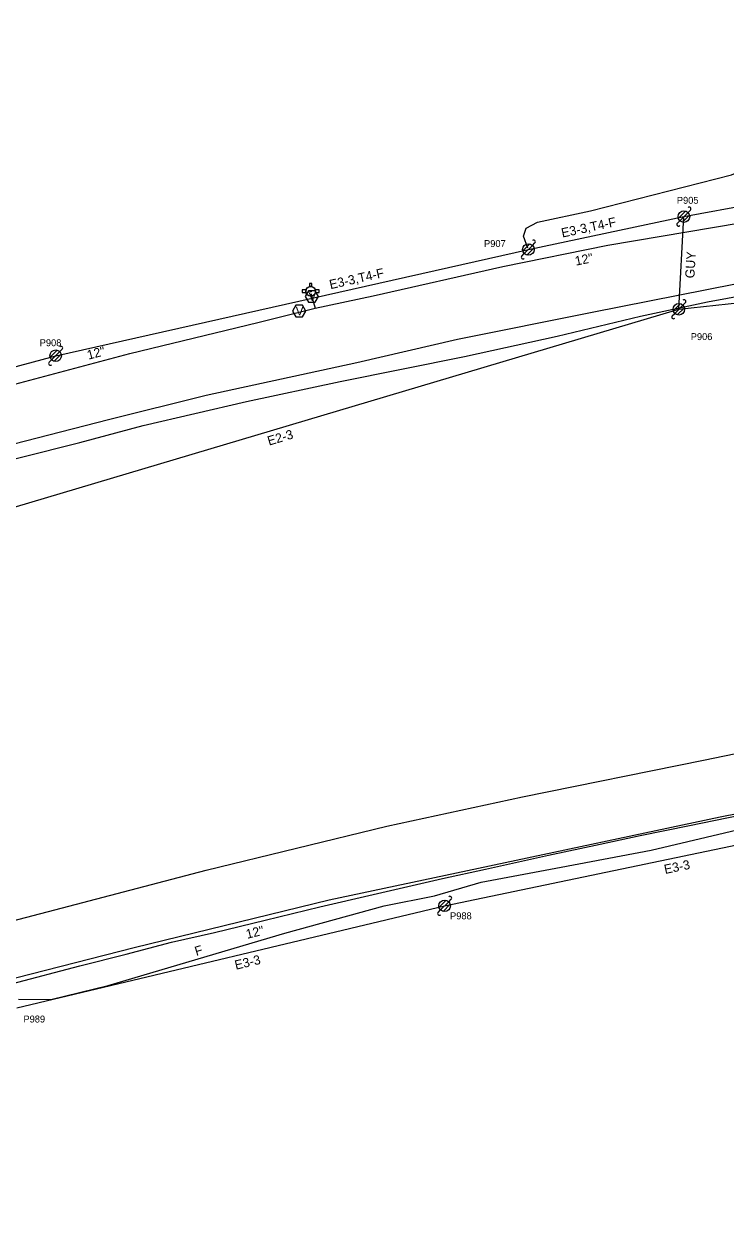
# Model space of a CAD drawing. Extents: x 1741604 to 1825760, y 1164229 to 1194908.
# Drawn here: x 1797026 to 1797330, y 1187911 to 1188433 of the extents above; entities that cross this region are included whole.
import ezdxf

# ---------------------------------------------------------------- set-up
doc = ezdxf.new("R2010")
doc.units = 0
for name, color, linetype in [('RD_EX_SU_Elec', 7, 'Continuous'), ('RD_EX_SU_Gas', 7, 'Continuous'), ('RD_EX_SU_H2O', 7, 'Continuous'), ('RD_EX_SU_Ovhd', 7, 'Continuous'), ('RD_EX_SU_Pole', 7, 'Continuous'), ('RD_EX_SU_Telecom', 7, 'Continuous'), ('RD_EX_SU_TX_H2O', 7, 'Continuous'), ('RD_EX_SU_TX_Pole', 7, 'Continuous'), ('RD_EX_SU_TX_Telecom', 7, 'Continuous')]:
    doc.layers.add(name, color=color, linetype=linetype)

# ---------------------------------------------------------------- blocks, each defined once
blk = doc.blocks.new('SUE_WFH')
at = {"layer": 'RD_EX_SU_H2O'}
for p, q in [((-2.01, 0.6), (-3.65, 0.6)), ((-3.65, 0.6), (-3.65, -0.45)), ((-0.48, 3.38), (-0.48, 2.04)), ((0.57, 3.38), (-0.48, 3.38)), ((0.57, 2.02), (0.57, 3.38)), ((3.7, 0.6), (2.01, 0.6)), ((3.7, -0.45), (3.7, 0.6)), ((-3.65, -0.45), (-2.05, -0.45)), ((2.05, -0.45), (3.7, -0.45))]:
    blk.add_line(p, q, dxfattribs=at)
for radius in [2.1, 0.263]:
    blk.add_circle((0, 0), radius, dxfattribs=at)
for start, end in [(163.3387, 192.315), (74.2455, 103.2128), (347.685, 16.6613)]:
    blk.add_arc((0, 0), 2.1, start, end, dxfattribs=at)
blk = doc.blocks.new('SUE_WV')
at = {"layer": 'RD_EX_SU_H2O'}
blk.add_lwpolyline([(2.89, 0), (1.44, 2.5), (-1.44, 2.5), (-2.89, 0), (-1.44, -2.5), (1.44, -2.5)], close=True, dxfattribs=at)
blk.add_text('V', height=3.75, dxfattribs=at).set_placement((-1.43, -1.88))
blk = doc.blocks.new('SUE_PP')
at = {"layer": 'RD_EX_SU_Pole'}
for p, q in [((-2.41, -0.65), (0.65, 2.41)), ((-1.77, -1.77), (1.77, 1.77)), ((-0.65, -2.41), (2.41, 0.65)), ((1.77, 1.77), (2.83, 2.83)), ((-2.83, -2.83), (-1.77, -1.77))]:
    blk.add_line(p, q, dxfattribs=at)
blk.add_circle((0, 0), 2.5, dxfattribs=at)
for centre, start, end in [((2.3, 3.36), 315, 135), ((-2.3, -3.36), 135, 315)]:
    blk.add_arc(centre, 0.75, start, end, dxfattribs=at)

msp = doc.modelspace()

# ---------------------------------------------------------------- linework, layer by layer
at = {"layer": 'RD_EX_SU_Elec'}
msp.add_lwpolyline([(1797244.36, 1188335.69), (1797242.43, 1188340.91), (1797243.62, 1188344.36), (1797248.47, 1188347.06), (1797271.46, 1188351.92), (1797332.51, 1188367.48), (1797339.83, 1188370.66), (1797346.01, 1188378.93), (1797354.24, 1188382.3), (1797365.1, 1188383.61), (1797373.13, 1188384.12)], dxfattribs=at)
at = {"layer": 'RD_EX_SU_Gas'}
for points in [[(1796999.22, 1188238.71), (1797050.44, 1188251.64), (1797077.75, 1188259.02), (1797122.56, 1188269.33), (1797163.15, 1188277.98), (1797216.98, 1188288.79), (1797257.11, 1188297.58), (1797293.17, 1188306.24), (1797322.16, 1188312.53), (1797378.04, 1188322.78), (1797422.78, 1188329.89), (1797468.29, 1188337.79), (1797507.29, 1188344.04), (1797536.09, 1188348.16), (1797575.83, 1188353.54), (1797616.9, 1188360.18), (1797661.37, 1188365.53), (1797707.78, 1188370.84), (1797750.95, 1188375.94), (1797792.89, 1188381.02), (1797883.32, 1188390.89)], [(1796656.1, 1187911.21), (1796700.26, 1187926.24), (1796776.05, 1187949.97), (1796853.24, 1187973.45), (1796908.86, 1187989.52), (1796990.78, 1188011.87), (1797073.97, 1188032.99), (1797158.33, 1188053.63), (1797222.98, 1188067.43), (1797327.66, 1188089.58), (1797395.86, 1188103.05), (1797465.31, 1188115.89), (1797490.6, 1188120.59), (1797504.29, 1188121.55), (1797523.16, 1188120.37), (1797539.47, 1188121.55), (1797556.07, 1188120.37), (1797575.66, 1188121.89)]]:
    msp.add_lwpolyline(points, dxfattribs=at)
at = {"layer": 'RD_EX_SU_H2O'}
for points in [[(1797150.37, 1188316.12), (1797152.28, 1188309.78), (1797177.44, 1188315.15), (1797233.5, 1188327.84), (1797278.93, 1188337.07), (1797336.23, 1188346.78), (1797380.95, 1188356.35), (1797444.61, 1188369.17), (1797512.17, 1188378.38), (1797550.95, 1188385.16), (1797589.68, 1188391.31), (1797635.24, 1188397.02), (1797695.71, 1188404.5), (1797752.4, 1188412.16), (1797828.2, 1188420.96), (1797864.18, 1188424.5), (1797870.03, 1188425), (1797870.01, 1188429.58), (1797869.79, 1188432.74)], [(1796441.83, 1188109.93), (1796444.87, 1188101.29), (1796539.94, 1188133.72), (1796647.13, 1188169.94), (1796712.18, 1188190.57), (1796798.06, 1188216.42), (1796872.26, 1188237.32), (1796925.71, 1188251.76), (1796989.63, 1188268.23), (1797072.11, 1188290.16), (1797127.52, 1188303.54), (1797152.28, 1188309.78)], [(1797020.74, 1188017.27), (1797050.38, 1188025.03), (1797070.49, 1188030.17), (1797090.04, 1188035.3), (1797108.74, 1188039.51), (1797130.56, 1188044.84), (1797154.31, 1188050.59), (1797177.42, 1188056.02), (1797207.46, 1188062.85), (1797225.98, 1188066.97), (1797253.33, 1188072.94), (1797275.68, 1188077.76), (1797293.01, 1188081.5), (1797314.36, 1188085.8), (1797336.2, 1188090.35), (1797355.18, 1188094.27), (1797378.17, 1188098.87), (1797401.5, 1188103.47), (1797420.73, 1188107.13), (1797437.47, 1188110.13), (1797458.81, 1188113.91), (1797484.19, 1188118.42), (1797507.62, 1188122.44), (1797519.17, 1188124.46)]]:
    msp.add_lwpolyline(points, dxfattribs=at)
at = {"layer": 'RD_EX_SU_Ovhd'}
for p, q in [((1797311.92, 1188349.39), (1797455.11, 1188375.73)), ((1797244.57, 1188335.16), (1797311.92, 1188349.39)), ((1797309.7, 1188309.3), (1797311.92, 1188349.39)), ((1797039.93, 1188289.19), (1797244.57, 1188335.16)), ((1797309.7, 1188309.3), (1797485.34, 1188328.33)), ((1796963.44, 1188206.26), (1797309.7, 1188309.3)), ((1796830.97, 1188232.5), (1797039.93, 1188289.19)), ((1797208.33, 1188051.07), (1797439.47, 1188099.21)), ((1797023.16, 1188006.96), (1797208.33, 1188051.07))]:
    msp.add_line(p, q, dxfattribs=at)
at = {"layer": 'RD_EX_SU_Pole'}
for p, q in [((1797309.51, 1188348.74), (1797312.57, 1188351.8)), ((1797310.16, 1188347.62), (1797313.69, 1188351.16)), ((1797311.28, 1188346.97), (1797314.34, 1188350.03)), ((1797313.69, 1188351.16), (1797314.75, 1188352.22)), ((1797309.09, 1188346.56), (1797310.16, 1188347.62)), ((1797242.16, 1188334.52), (1797245.22, 1188337.58)), ((1797242.81, 1188333.4), (1797246.34, 1188336.93)), ((1797243.93, 1188332.75), (1797246.99, 1188335.81)), ((1797246.34, 1188336.93), (1797247.4, 1188337.99)), ((1797241.75, 1188332.34), (1797242.81, 1188333.4)), ((1797037.1, 1188286.36), (1797038.16, 1188287.42)), ((1797037.52, 1188288.54), (1797040.58, 1188291.61)), ((1797038.16, 1188287.42), (1797041.7, 1188290.96)), ((1797039.28, 1188286.78), (1797042.35, 1188289.84)), ((1797041.7, 1188290.96), (1797042.76, 1188292.02)), ((1797205.92, 1188050.42), (1797208.98, 1188053.48)), ((1797206.57, 1188049.3), (1797210.1, 1188052.84)), ((1797210.1, 1188052.84), (1797211.16, 1188053.9)), ((1797205.5, 1188048.24), (1797206.57, 1188049.3)), ((1797207.69, 1188048.65), (1797210.75, 1188051.72))]:
    msp.add_line(p, q, dxfattribs=at)
for centre in [(1797311.92, 1188349.39), (1797244.57, 1188335.16), (1797039.93, 1188289.19), (1797208.33, 1188051.07)]:
    msp.add_circle(centre, 2.5, dxfattribs=at)
for centre, start, end in [((1797314.22, 1188352.75), 315, 135), ((1797309.62, 1188346.03), 135, 315), ((1797246.87, 1188338.52), 315, 135), ((1797242.28, 1188331.81), 135, 315), ((1797042.23, 1188292.55), 315, 135), ((1797037.63, 1188285.83), 135, 315), ((1797210.63, 1188054.43), 315, 135), ((1797206.04, 1188047.71), 135, 315)]:
    msp.add_arc(centre, 0.75, start, end, dxfattribs=at)
at = {"layer": 'RD_EX_SU_Telecom'}
for points in [[(1796980.05, 1188240.41), (1797062.85, 1188261.56), (1797105.15, 1188272.12), (1797170.25, 1188286.3), (1797213.92, 1188296.36), (1797272.18, 1188308.04), (1797346.72, 1188322.81), (1797409.42, 1188334.04), (1797437.93, 1188338.58), (1797442.26, 1188336.49)], [(1796981.04, 1188034.01), (1797045.59, 1188050.89), (1797105.03, 1188066.54), (1797183.3, 1188085.53), (1797242.02, 1188098.21), (1797320.33, 1188114.14), (1797360.89, 1188122.43), (1797421.68, 1188134.56), (1797471.7, 1188142.95), (1797502.71, 1188148.5), (1797507.43, 1188146.36), (1797511.96, 1188125.64), (1797514.01, 1188119.83), (1797517.93, 1188118.25), (1797545.42, 1188119.45), (1797561.4, 1188118.32), (1797576.27, 1188111.25), (1797581.53, 1188106.35), (1797597.76, 1188086.02), (1797625.77, 1188046.93), (1797641.23, 1188023.98)], [(1797023.77, 1188010.64), (1797037.78, 1188010.54), (1797062.6, 1188016.54), (1797139.08, 1188039.2), (1797182.21, 1188051.12), (1797203.98, 1188055.44), (1797224.21, 1188061.27), (1797258.79, 1188067.75), (1797297.7, 1188075.12), (1797337.47, 1188084.59), (1797392.31, 1188093.68), (1797434.61, 1188100.23), (1797472.95, 1188106.33), (1797494.95, 1188108.9), (1797517.98, 1188113.3), (1797537.71, 1188117.73), (1797543.52, 1188116.73)]]:
    msp.add_lwpolyline(points, dxfattribs=at)

# ---------------------------------------------------------------- block references
at = {"layer": 'RD_EX_SU_H2O'}
for name, p in [('SUE_WFH', (1797150.32, 1188317.04)), ('SUE_WV', (1797150.81, 1188314.82)), ('SUE_WV', (1797145.29, 1188308.54))]:
    msp.add_blockref(name, p, dxfattribs=at)
at = {"layer": 'RD_EX_SU_Pole'}
msp.add_blockref('SUE_PP', (1797309.7, 1188309.3), dxfattribs=at)

# ---------------------------------------------------------------- texts
at = {"layer": 'RD_EX_SU_Ovhd'}
for s, rotation, p in [('E3-3,T4-F', 11.9248, (1797259.29, 1188340.32)), ('GUY', 86.8194, (1797316.44, 1188322.6)), ('E3-3,T4-F', 12.6615, (1797158.91, 1188317.97)), ('E2-3', 16.5717, (1797132.3, 1188250.25)), ('E3-3', 11.7655, (1797303.79, 1188064.82)), ('E3-3', 13.3998, (1797117.96, 1188023.37))]:
    msp.add_text(s, height=4, rotation=rotation, dxfattribs=at).set_placement(p)
at = {"layer": 'RD_EX_SU_TX_H2O'}
for rotation, p in [(11.4823, (1797265.19, 1188328.16)), (14.887, (1797054.11, 1188287.44)), (13.7293, (1797122.83, 1188036.77))]:
    msp.add_text('12"', height=4, rotation=rotation, dxfattribs=at).set_placement(p)
at = {"layer": 'RD_EX_SU_TX_Pole'}
for s, p in [('P905', (1797308.87, 1188354.96)), ('P907', (1797225.4, 1188336.22)), ('P906', (1797314.88, 1188295.95)), ('P908', (1797033.03, 1188293.31)), ('P988', (1797210.68, 1188045.23)), ('P989', (1797025.98, 1188000.56))]:
    msp.add_text(s, height=3, dxfattribs=at).set_placement(p)
at = {"layer": 'RD_EX_SU_TX_Telecom'}
msp.add_text('F', height=4, rotation=16.5058, dxfattribs=at).set_placement((1797100.81, 1188029.34))

doc.saveas('drawing.dxf')
